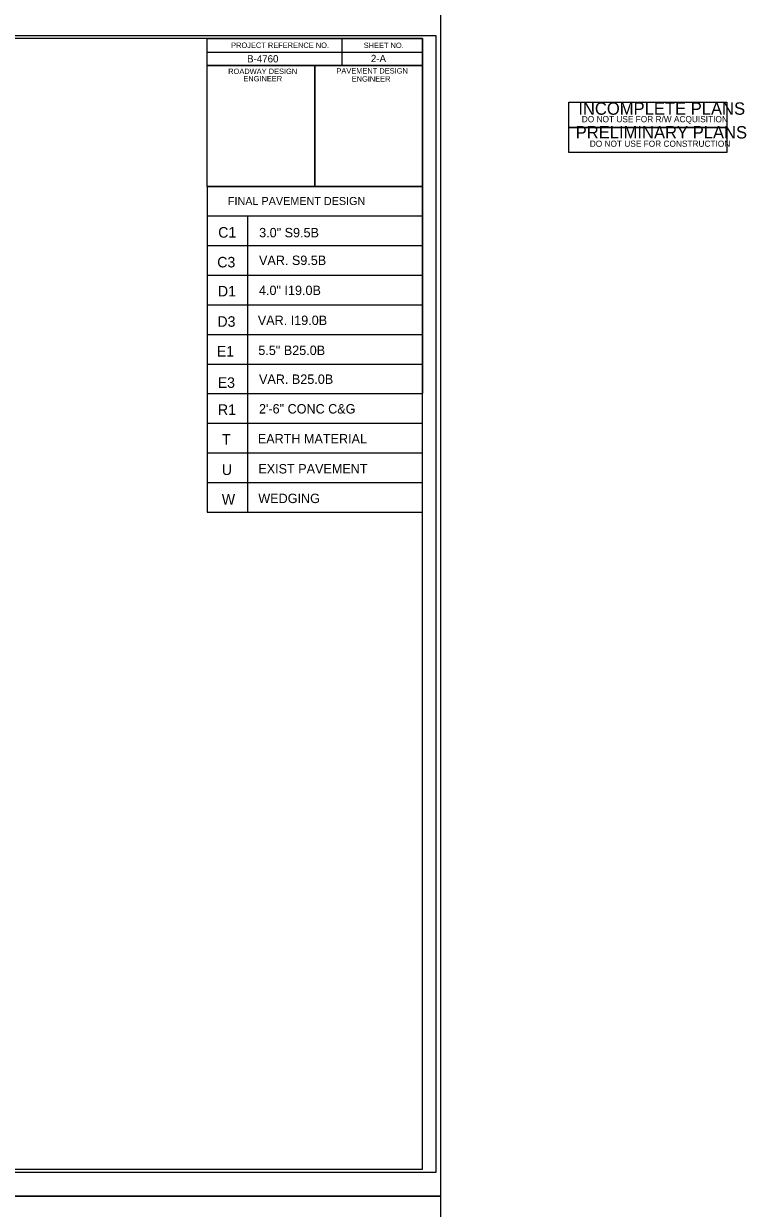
# Model space of a CAD drawing. Extents: x 981824 to 982276, y 44828 to 45204.
# Drawn here: x 982198.1 to 982251.8, y 45001.1 to 45089.1 of the extents above; entities that cross this region are included whole.
import ezdxf

# ---------------------------------------------------------------- set-up
doc = ezdxf.new("R2010")
doc.units = 0
for name, color, linetype in [('Old_Level_1', 7, 'Continuous'), ('Old_Level_18', 7, 'Continuous'), ('Old_Level_19', 7, 'Continuous'), ('Old_Level_21', 7, 'Continuous'), ('Old_Level_40', 7, 'Continuous'), ('Old_Level_44', 7, 'Continuous'), ('Old_Level_50', 7, 'Continuous'), ('Old_Level_51', 7, 'Continuous'), ('Old_Level_52', 7, 'Continuous'), ('Sheet Sticker Incomplete CELL', 7, 'Continuous'), ('Sheet Sticker Preliminary CELL', 7, 'Continuous')]:
    doc.layers.add(name, color=color, linetype=linetype)

msp = doc.modelspace()

# ---------------------------------------------------------------- linework, layer by layer
at = {"layer": 'Old_Level_1'}
msp.add_line((982228.72, 45088.173), (982228.72, 45088.173), dxfattribs=at)
at = {"layer": 'Old_Level_18'}
msp.add_lwpolyline([(982227.72, 45087.969), (982107.72, 45087.969), (982107.72, 45003.969), (982227.72, 45003.969)], close=True, dxfattribs=at)
at = {"layer": 'Old_Level_19'}
for p, q in [((982211.716, 45076.965), (982227.72, 45076.965)), ((982211.716, 45076.965), (982211.716, 45052.791)), ((982227.72, 45076.965), (982227.72, 45061.591)), ((982211.716, 45074.791), (982227.72, 45074.791)), ((982214.716, 45074.791), (982214.716, 45052.791)), ((982211.716, 45072.591), (982227.72, 45072.591)), ((982211.716, 45070.391), (982227.72, 45070.391)), ((982211.716, 45068.191), (982227.72, 45068.191)), ((982211.716, 45065.991), (982227.72, 45065.991)), ((982211.716, 45063.791), (982227.72, 45063.791)), ((982211.716, 45061.591), (982227.72, 45061.591)), ((982211.716, 45059.391), (982227.72, 45059.391)), ((982211.716, 45057.191), (982227.72, 45057.191)), ((982211.716, 45054.991), (982227.72, 45054.991)), ((982211.716, 45052.791), (982227.72, 45052.791))]:
    msp.add_line(p, q, dxfattribs=at)
at = {"layer": 'Old_Level_40'}
for p, q in [((982221.72, 45087.965), (982221.72, 45085.965)), ((982211.716, 45086.965), (982227.72, 45086.965)), ((982219.72, 45085.965), (982219.72, 45076.969))]:
    msp.add_line(p, q, dxfattribs=at)
for points in [[(982211.716, 45087.969), (982227.72, 45087.969), (982227.72, 45085.965), (982211.716, 45085.965)], [(982211.716, 45085.965), (982219.72, 45085.965), (982219.72, 45076.965), (982211.716, 45076.965)], [(982219.72, 45085.965), (982227.72, 45085.965), (982227.72, 45076.965), (982219.72, 45076.965)]]:
    msp.add_lwpolyline(points, close=True, dxfattribs=at)
at = {"layer": 'Old_Level_50'}
msp.add_line((982229.08, 45001.969), (982229.08, 45001.969), dxfattribs=at)
msp.add_lwpolyline([(982228.72, 45088.173), (982095.4, 45088.173), (982095.4, 45003.765), (982228.72, 45003.765)], close=True, dxfattribs=at)
at = {"layer": 'Old_Level_51'}
for points in [[(982229.08, 45089.969), (982094.36, 45089.969), (982094.36, 45001.969), (982229.08, 45001.969)], [(982229.08, 45001.969), (982094.36, 45001.969), (982094.36, 44913.969), (982229.08, 44913.969)]]:
    msp.add_lwpolyline(points, close=True, dxfattribs=at)
at = {"layer": 'Old_Level_52'}
msp.add_line((982228.72, 45088.173), (982228.72, 45088.173), dxfattribs=at)
at = {"layer": 'Sheet Sticker Incomplete CELL'}
msp.add_lwpolyline([(982238.579, 45081.371), (982238.579, 45083.251), (982250.339, 45083.251), (982250.339, 45081.371)], close=True, dxfattribs=at)
at = {"layer": 'Sheet Sticker Preliminary CELL'}
msp.add_lwpolyline([(982238.579, 45079.491), (982238.579, 45081.371), (982250.339, 45081.371), (982250.339, 45079.491)], close=True, dxfattribs=at)

# ---------------------------------------------------------------- texts
at = {"layer": 'Old_Level_21'}
for s, height, p in [('FINAL PAVEMENT DESIGN', 0.6, (982213.253, 45075.599)), ('C1 ', 0.784, (982212.531, 45073.178)), ('3.0" S9.5B', 0.7, (982215.575, 45073.2)), ('VAR. S9.5B', 0.7, (982215.564, 45071.145)), ('C3', 0.784, (982212.461, 45070.965)), ('D1 ', 0.784, (982212.51, 45068.811)), ('4.0" I19.0B', 0.7, (982215.564, 45068.913)), ('D3', 0.784, (982212.474, 45066.555)), ('VAR. I19.0B', 0.7, (982215.476, 45066.688)), ('E1 ', 0.784, (982212.427, 45064.345)), ('5.5" B25.0B', 0.7, (982215.514, 45064.459)), ('E3', 0.784, (982212.495, 45062.018)), ('VAR. B25.0B', 0.7, (982215.564, 45062.313)), ('R1 ', 0.784, (982212.51, 45060.011)), ('2\'-6" CONC C&G', 0.7, (982215.564, 45060.113)), ('T ', 0.784, (982212.826, 45057.799)), ('EARTH MATERIAL', 0.7, (982215.476, 45057.888)), ('U ', 0.784, (982212.799, 45055.545)), ('EXIST PAVEMENT', 0.7, (982215.514, 45055.659)), ('W ', 0.784, (982212.799, 45053.345)), ('WEDGING', 0.7, (982215.514, 45053.459))]:
    msp.add_text(s, height=height, dxfattribs=at).set_placement(p)
at = {"layer": 'Old_Level_44'}
for s, height, p in [('PROJECT REFERENCE NO.', 0.40001, (982213.492, 45087.273)), ('SHEET NO.', 0.4, (982223.344, 45087.265)), (' B-4760 ', 0.54, (982214.478, 45086.193)), ('2-A', 0.54, (982223.88, 45086.217)), ('ROADWAY DESIGN', 0.40001, (982213.276, 45085.333)), ('ENGINEER', 0.4, (982214.4, 45084.785)), ('PAVEMENT DESIGN', 0.40001, (982221.316, 45085.369)), ('ENGINEER', 0.4, (982222.452, 45084.773))]:
    msp.add_text(s, height=height, dxfattribs=at).set_placement(p)
at = {"layer": 'Sheet Sticker Incomplete CELL'}
for s, height, p in [('INCOMPLETE PLANS', 0.9216, (982239.295, 45082.307)), ('DO NOT USE FOR R/W ACQUISITION', 0.4608, (982239.555, 45081.751))]:
    msp.add_text(s, height=height, dxfattribs=at).set_placement(p)
at = {"layer": 'Sheet Sticker Preliminary CELL'}
for s, height, p in [('PRELIMINARY PLANS', 0.9216, (982239.099, 45080.543)), ('DO NOT USE FOR CONSTRUCTION', 0.4608, (982240.147, 45079.927))]:
    msp.add_text(s, height=height, dxfattribs=at).set_placement(p)

doc.saveas('drawing.dxf')
